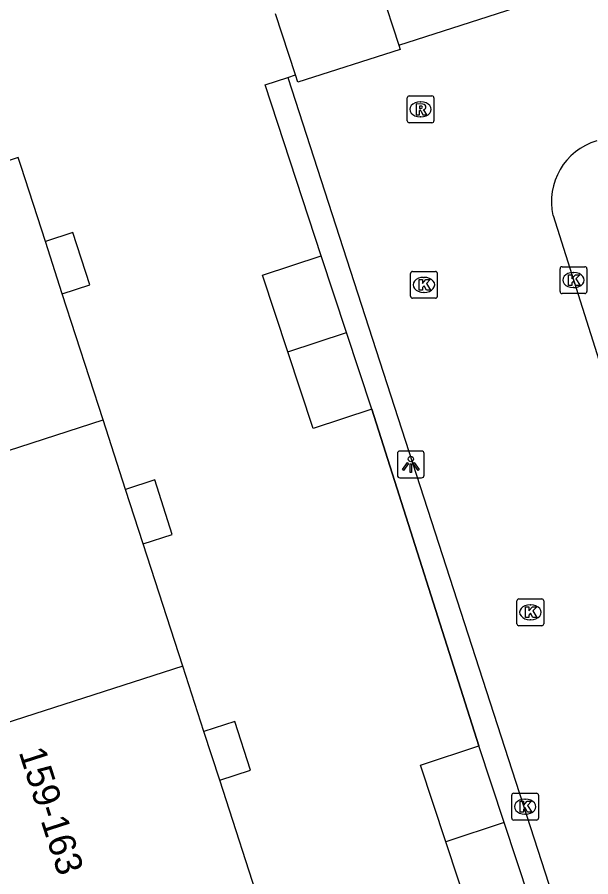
# Model space of a CAD drawing. Extents: x 159377 to 159983, y 382996 to 383595.
# Drawn here: x 159502.21 to 159523.61, y 383092.94 to 383125.01 of the extents above; entities that cross this region are included whole.
import ezdxf

# ---------------------------------------------------------------- set-up
doc = ezdxf.new("R2010")
doc.units = 0
for name, color, linetype in [('IMGEO_Kolk', 7, 'Continuous'), ('IMGEO_Lichtpunt', 7, 'Continuous'), ('IMGEO_Muur', 7, 'Continuous'), ('IMGEO_Pand', 7, 'Continuous'), ('IMGEO_Pand_nummerreeks', 7, 'Continuous'), ('IMGEO_Rijbaan_lokaal_open', 7, 'Continuous'), ('IMGEO_Rioolput', 7, 'Continuous'), ('IMGEO_Voetpad_open', 7, 'Continuous')]:
    doc.layers.add(name, color=color, linetype=linetype)

msp = doc.modelspace()

# ---------------------------------------------------------------- linework, layer by layer
at = {"layer": 'IMGEO_Kolk'}
for p, q in [((159522.466, 383114.778), (159522.466, 383115.63)), ((159522.541, 383115.704), (159523.393, 383115.704)), ((159523.467, 383115.63), (159523.467, 383114.778)), ((159516.886, 383114.601), (159516.886, 383115.453)), ((159516.961, 383115.527), (159517.813, 383115.527)), ((159517.374, 383115.307), (159517.399, 383115.307)), ((159517.887, 383115.453), (159517.887, 383114.601)), ((159522.954, 383115.484), (159522.979, 383115.484)), ((159517.397, 383114.747), (159517.372, 383114.747)), ((159523.393, 383114.704), (159522.541, 383114.704)), ((159522.977, 383114.924), (159522.952, 383114.924)), ((159517.813, 383114.527), (159516.961, 383114.527)), ((159520.859, 383102.385), (159520.859, 383103.237)), ((159520.934, 383103.311), (159521.786, 383103.311)), ((159521.86, 383103.237), (159521.86, 383102.385)), ((159521.347, 383103.091), (159521.372, 383103.091)), ((159521.37, 383102.531), (159521.345, 383102.531)), ((159521.786, 383102.311), (159520.934, 383102.311)), ((159520.662, 383095.132), (159520.662, 383095.984)), ((159520.737, 383096.058), (159521.589, 383096.058)), ((159521.15, 383095.838), (159521.175, 383095.838)), ((159521.663, 383095.984), (159521.663, 383095.132)), ((159521.173, 383095.278), (159521.148, 383095.278)), ((159521.589, 383095.058), (159520.737, 383095.058))]:
    msp.add_line(p, q, dxfattribs=at)
for points in [[(159522.466, 383114.778), (159522.466, 383115.63)], [(159522.541, 383115.704), (159523.393, 383115.704)], [(159523.467, 383115.63), (159523.467, 383114.778)], [(159516.886, 383114.601), (159516.886, 383115.453)], [(159516.961, 383115.527), (159517.813, 383115.527)], [(159517.887, 383115.453), (159517.887, 383114.601)], [(159522.787, 383115.404), (159522.91, 383115.404), (159522.91, 383115.253), (159523.04, 383115.404), (159523.204, 383115.404), (159523.058, 383115.253), (159523.211, 383115.004), (159523.059, 383115.004), (159522.974, 383115.168), (159522.91, 383115.101), (159522.91, 383115.004), (159522.787, 383115.004), (159522.787, 383115.404)], [(159517.207, 383115.227), (159517.33, 383115.227), (159517.33, 383115.076), (159517.46, 383115.227), (159517.624, 383115.227), (159517.478, 383115.076), (159517.631, 383114.827), (159517.479, 383114.827), (159517.394, 383114.991), (159517.33, 383114.924), (159517.33, 383114.827), (159517.207, 383114.827), (159517.207, 383115.227)], [(159523.393, 383114.704), (159522.541, 383114.704)], [(159517.813, 383114.527), (159516.961, 383114.527)], [(159520.859, 383102.385), (159520.859, 383103.237)], [(159520.934, 383103.311), (159521.786, 383103.311)], [(159521.86, 383103.237), (159521.86, 383102.385)], [(159521.18, 383103.011), (159521.303, 383103.011), (159521.303, 383102.86), (159521.433, 383103.011), (159521.597, 383103.011), (159521.451, 383102.86), (159521.604, 383102.611), (159521.452, 383102.611), (159521.367, 383102.775), (159521.303, 383102.708), (159521.303, 383102.611), (159521.18, 383102.611), (159521.18, 383103.011)], [(159521.786, 383102.311), (159520.934, 383102.311)], [(159520.662, 383095.132), (159520.662, 383095.984)], [(159520.737, 383096.058), (159521.589, 383096.058)], [(159520.983, 383095.758), (159521.106, 383095.758), (159521.106, 383095.607), (159521.236, 383095.758), (159521.4, 383095.758), (159521.254, 383095.607), (159521.407, 383095.358), (159521.255, 383095.358), (159521.17, 383095.522), (159521.106, 383095.455), (159521.106, 383095.358), (159520.983, 383095.358), (159520.983, 383095.758)], [(159521.663, 383095.984), (159521.663, 383095.132)], [(159521.589, 383095.058), (159520.737, 383095.058)]]:
    msp.add_lwpolyline(points, dxfattribs=at)
for centre, start, end in [((159522.543, 383115.628), 91.552, 178.448), ((159522.543, 383115.628), 91.552, 178.448), ((159523.391, 383115.628), 1.552, 88.448), ((159523.391, 383115.628), 1.552, 88.448), ((159516.963, 383115.451), 91.552, 178.448), ((159516.963, 383115.451), 91.552, 178.448), ((159517.811, 383115.451), 1.552, 88.448), ((159517.811, 383115.451), 1.552, 88.448), ((159522.543, 383114.78), 181.552, 268.448), ((159522.543, 383114.78), 181.552, 268.448), ((159523.391, 383114.78), 271.552, 358.448), ((159523.391, 383114.78), 271.552, 358.448), ((159516.963, 383114.603), 181.552, 268.448), ((159516.963, 383114.603), 181.552, 268.448), ((159517.811, 383114.603), 271.552, 358.448), ((159517.811, 383114.603), 271.552, 358.448), ((159520.936, 383103.235), 91.552, 178.448), ((159520.936, 383103.235), 91.552, 178.448), ((159521.784, 383103.235), 1.552, 88.448), ((159521.784, 383103.235), 1.552, 88.448), ((159520.936, 383102.387), 181.552, 268.448), ((159520.936, 383102.387), 181.552, 268.448), ((159521.784, 383102.387), 271.552, 358.448), ((159521.784, 383102.387), 271.552, 358.448), ((159520.739, 383095.982), 91.552, 178.448), ((159520.739, 383095.982), 91.552, 178.448), ((159521.587, 383095.982), 1.552, 88.448), ((159521.587, 383095.982), 1.552, 88.448), ((159520.739, 383095.134), 181.552, 268.448), ((159520.739, 383095.134), 181.552, 268.448), ((159521.587, 383095.134), 271.552, 358.448), ((159521.587, 383095.134), 271.552, 358.448)]:
    msp.add_arc(centre, 0.0765, start, end, dxfattribs=at)
for centre, major_axis, ratio, start_param, end_param in [((159517.373, 383115.027), (-0.387, 0.002), 0.722429, 4.712389, 7.853982), ((159517.398, 383115.027), (-0.39, 0.002), 0.717154, 1.570796, 4.712389), ((159522.953, 383115.204), (-0.387, 0.002), 0.722429, 4.712389, 7.853982), ((159522.978, 383115.204), (-0.39, 0.002), 0.717154, 1.570796, 4.712389), ((159521.346, 383102.811), (-0.387, 0.002), 0.722429, 4.712389, 7.853982), ((159521.371, 383102.811), (-0.39, 0.002), 0.717154, 1.570796, 4.712389), ((159521.149, 383095.558), (-0.387, 0.002), 0.722429, 4.712389, 7.853982), ((159521.174, 383095.558), (-0.39, 0.002), 0.717154, 1.570796, 4.712389)]:
    msp.add_ellipse(centre, major_axis=major_axis, ratio=ratio, start_param=start_param, end_param=end_param, dxfattribs=at)
at = {"layer": 'IMGEO_Lichtpunt'}
for p, q in [((159516.399, 383108.731), (159516.399, 383107.924)), ((159516.399, 383108.731), (159516.399, 383107.924)), ((159517.301, 383108.826), (159516.493, 383108.826)), ((159517.301, 383108.826), (159516.493, 383108.826)), ((159517.395, 383107.924), (159517.395, 383108.731)), ((159517.395, 383107.924), (159517.395, 383108.731)), ((159516.493, 383107.83), (159517.301, 383107.83)), ((159516.493, 383107.83), (159517.301, 383107.83))]:
    msp.add_line(p, q, dxfattribs=at)
for points in [[(159516.773, 383108.395), (159516.812, 383108.367), (159516.624, 383108.105), (159516.586, 383108.132), (159516.773, 383108.395)], [(159516.875, 383108.347), (159516.922, 383108.347), (159516.922, 383108.025), (159516.875, 383108.025), (159516.875, 383108.347)], [(159516.985, 383108.367), (159517.023, 383108.394), (159517.21, 383108.132), (159517.171, 383108.104), (159516.985, 383108.367)]]:
    msp.add_lwpolyline(points, dxfattribs=at)
msp.add_circle((159516.898, 383108.529), 0.0994, dxfattribs=at)
for centre, start, end in [((159516.493, 383108.731), 90, 180), ((159516.493, 383108.731), 90, 180), ((159517.301, 383108.731), 0, 90), ((159517.301, 383108.731), 0, 90), ((159516.493, 383107.924), 180, 270), ((159516.493, 383107.924), 180, 270), ((159517.301, 383107.924), 270, 0), ((159517.301, 383107.924), 270, 360)]:
    msp.add_arc(centre, 0.0946, start, end, dxfattribs=at)
at = {"layer": 'IMGEO_Muur'}
msp.add_lwpolyline([(159515.44, 383110.383), (159519.44, 383097.832)], dxfattribs=at)
at = {"layer": 'IMGEO_Pand'}
for points in [[(159515.767, 383126.073), (159516.455, 383123.963)], [(159512.597, 383122.856), (159511.855, 383125.134)], [(159516.455, 383123.963), (159516.506, 383123.807), (159512.682, 383122.594), (159512.597, 383122.856)], [(159503.263, 383116.643), (159502.357, 383119.441), (159502.248, 383119.779), (159500.377, 383119.171)], [(159503.893, 383114.696), (159504.923, 383115.029), (159504.293, 383116.976), (159503.263, 383116.643)], [(159503.893, 383114.696), (159503.263, 383116.643)], [(159512.311, 383112.525), (159511.367, 383115.388), (159513.551, 383116.108)], [(159514.496, 383113.246), (159513.551, 383116.108)], [(159505.418, 383109.985), (159503.893, 383114.696)], [(159512.311, 383112.525), (159514.496, 383113.246)], [(159515.44, 383110.383), (159514.496, 383113.246)], [(159515.44, 383110.383), (159513.255, 383109.662), (159512.311, 383112.525)], [(159496.539, 383107.119), (159505.418, 383109.985)], [(159506.256, 383107.397), (159505.418, 383109.985)], [(159506.914, 383105.364), (159507.999, 383105.715), (159507.341, 383107.748), (159506.256, 383107.397)], [(159506.914, 383105.364), (159506.256, 383107.397)], [(159508.39, 383100.803), (159506.914, 383105.364)], [(159508.39, 383100.803), (159499.504, 383097.934)], [(159509.18, 383098.361), (159508.39, 383100.803)], [(159509.766, 383096.552), (159510.92, 383096.926), (159510.335, 383098.735), (159509.18, 383098.361)], [(159509.766, 383096.552), (159509.18, 383098.361)], [(159518.2, 383094.249), (159517.256, 383097.112), (159519.44, 383097.832)], [(159520.384, 383094.97), (159519.44, 383097.832)], [(159511.352, 383091.651), (159509.766, 383096.552)], [(159520.384, 383094.97), (159518.2, 383094.249)], [(159521.329, 383092.107), (159520.384, 383094.97)], [(159521.329, 383092.107), (159519.144, 383091.386), (159518.2, 383094.249)]]:
    msp.add_lwpolyline(points, dxfattribs=at)
at = {"layer": 'IMGEO_Rijbaan_lokaal_open'}
for points in [[(159516.455, 383123.963), (159541.49, 383132.018)], [(159512.311, 383122.762), (159512.597, 383122.856)], [(159512.311, 383122.762), (159522.735, 383090.553)], [(159522.203, 383117.611), (159526.631, 383103.627)]]:
    msp.add_lwpolyline(points, dxfattribs=at)
msp.add_arc((159524.516, 383118.131), 2.371, 106.6512, 192.6727, dxfattribs=at)
at = {"layer": 'IMGEO_Rioolput'}
for p, q in [((159516.836, 383122.074), (159517.688, 383122.074)), ((159516.761, 383121.148), (159516.761, 383122)), ((159517.249, 383121.854), (159517.274, 383121.854)), ((159517.762, 383122), (159517.762, 383121.148)), ((159517.272, 383121.294), (159517.247, 383121.294)), ((159517.688, 383121.074), (159516.836, 383121.074))]:
    msp.add_line(p, q, dxfattribs=at)
for points in [[(159516.836, 383122.074), (159517.688, 383122.074)], [(159516.761, 383121.148), (159516.761, 383122)], [(159517.35, 383121.772), (159517.098, 383121.774), (159517.098, 383121.374)], [(159517.762, 383122), (159517.762, 383121.148)], [(159517.098, 383121.374), (159517.222, 383121.374), (159517.222, 383121.536), (159517.233, 383121.536)], [(159517.276, 383121.693), (159517.222, 383121.693), (159517.222, 383121.612)], [(159517.222, 383121.612), (159517.274, 383121.612)], [(159517.28, 383121.507), (159517.351, 383121.374), (159517.491, 383121.374), (159517.426, 383121.5)], [(159517.688, 383121.074), (159516.836, 383121.074)]]:
    msp.add_lwpolyline(points, dxfattribs=at)
for centre, radius, start, end in [((159516.838, 383121.998), 0.0765, 91.552, 178.448), ((159516.838, 383121.998), 0.0765, 91.552, 178.448), ((159517.686, 383121.998), 0.0765, 1.552, 88.448), ((159517.686, 383121.998), 0.0765, 1.552, 88.448), ((159517.349, 383121.662), 0.109, 350.3612, 89.416), ((159517.232, 383121.483), 0.0533, 26.0293, 88.6989), ((159517.258, 383121.801), 0.19, 274.7715, 282.9687), ((159517.282, 383121.597), 0.0964, 77.0061, 93.1865), ((159517.296, 383121.654), 0.0378, 276.6634, 79.6772), ((159517.347, 383121.662), 0.112, 277.5842, 350.9817), ((159517.331, 383121.447), 0.108, 29.5134, 73.7905), ((159516.838, 383121.15), 0.0765, 181.552, 268.448), ((159516.838, 383121.15), 0.0765, 181.552, 268.448), ((159517.686, 383121.15), 0.0765, 271.552, 358.448), ((159517.686, 383121.15), 0.0765, 271.552, 358.448)]:
    msp.add_arc(centre, radius, start, end, dxfattribs=at)
for centre, major_axis, ratio, start_param, end_param in [((159517.248, 383121.574), (-0.387, 0.002), 0.722429, 4.712389, 7.853982), ((159517.273, 383121.574), (-0.39, 0.002), 0.717154, 1.570796, 4.712389)]:
    msp.add_ellipse(centre, major_axis=major_axis, ratio=ratio, start_param=start_param, end_param=end_param, dxfattribs=at)
at = {"layer": 'IMGEO_Voetpad_open'}
for points in [[(159513.551, 383116.108), (159511.46, 383122.485), (159512.311, 383122.762)], [(159519.44, 383097.832), (159515.44, 383110.383)]]:
    msp.add_lwpolyline(points, dxfattribs=at)

# ---------------------------------------------------------------- texts
at = {"layer": 'IMGEO_Pand_nummerreeks'}
msp.add_text('159-163', height=1, rotation=287.8016, dxfattribs=at).set_placement((159502.262, 383097.598))

doc.saveas('drawing.dxf')
